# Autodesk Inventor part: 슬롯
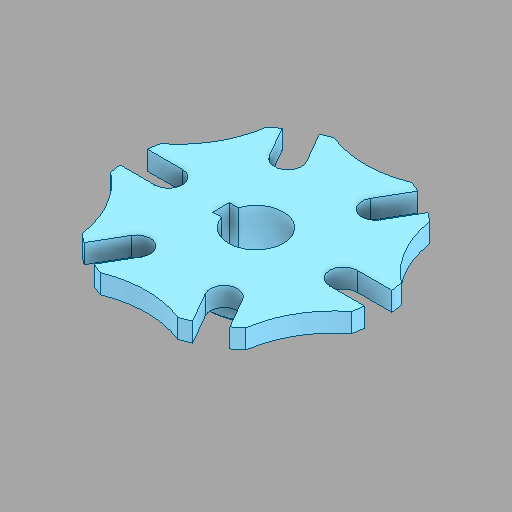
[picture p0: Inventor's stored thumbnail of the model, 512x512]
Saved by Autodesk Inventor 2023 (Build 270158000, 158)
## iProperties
Created: 2025-09
Part Number: 슬롯
Material: 강철, 합금
Document SubType Name: Modeling
Designer: home
Density: 7.73 g/cm^3
Appearance: 기본값
Author: jhkim
Sending System: Autodesk Inventor 2026
Preprocessor: ST-DEVELOPER v20.1
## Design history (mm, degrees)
feature "솔리드1"
node "솔리드2"
